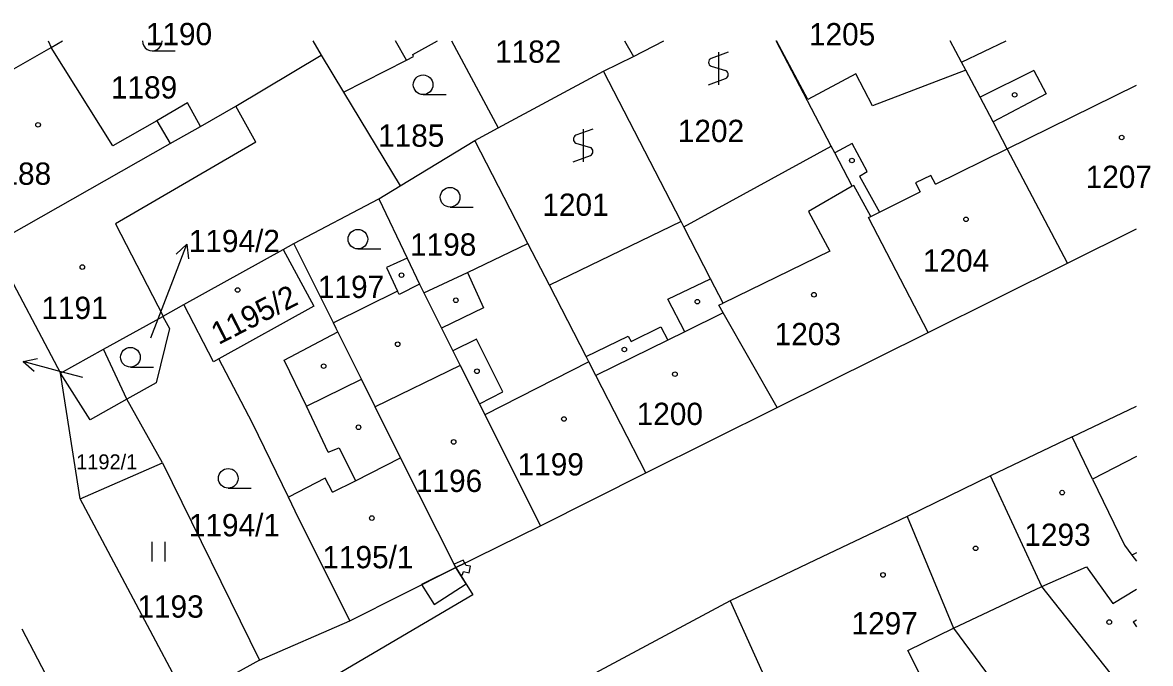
# Model space of a CAD drawing. Extents: x -600849 to -599899, y -1204328 to -1203436.
# Drawn here: x -599989.4 to -599903.3, y -1203485.7 to -1203436.8 of the extents above; entities that cross this region are included whole.
import ezdxf

# ---------------------------------------------------------------- set-up
doc = ezdxf.new("R2010")
doc.units = 0
for name, color, linetype in [('Vrstva 1', 7, 'Continuous'), ('Vrstva 13', 7, 'Continuous'), ('Vrstva 2', 7, 'Continuous'), ('Vrstva 3', 7, 'Continuous'), ('Vrstva 4', 7, 'Continuous'), ('Vrstva 5', 7, 'Continuous'), ('Vrstva 7', 7, 'Continuous')]:
    doc.layers.add(name, color=color, linetype=linetype)

msp = doc.modelspace()

# ---------------------------------------------------------------- linework, layer by layer
at = {"layer": 'Vrstva 1'}
for p, q in [((-599987.2, -1203438.69), (-599986.32, -1203438.183)), ((-599967.221, -1203438.183), (-599966.59, -1203439.27)), ((-599956.633, -1203438.183), (-599953.08, -1203444.83)), ((-599943.424, -1203438.183), (-599942.75, -1203439.37)), ((-599942.75, -1203439.37), (-599940.43, -1203438.183)), ((-599927.66, -1203446.22), (-599931.853, -1203438.183)), ((-599917.71, -1203439.81), (-599918.567, -1203438.183)), ((-599996.72, -1203444.1), (-599987.2, -1203438.69)), ((-599966.59, -1203439.27), (-599964.88, -1203442.11)), ((-599945.04, -1203440.5), (-599942.75, -1203439.37)), ((-599917.39, -1203440.42), (-599917.71, -1203439.81)), ((-599953.08, -1203444.83), (-599945.04, -1203440.5)), ((-599939.12, -1203451.96), (-599945.04, -1203440.5)), ((-599964.88, -1203442.11), (-599960.57, -1203449.26)), ((-599954.85, -1203445.79), (-599953.08, -1203444.83)), ((-599960.57, -1203449.26), (-599954.85, -1203445.79)), ((-599950.81, -1203453.64), (-599954.85, -1203445.79)), ((-599938.91, -1203452.38), (-599927.66, -1203446.22)), ((-599962.19, -1203450.25), (-599960.57, -1203449.26)), ((-599968.67, -1203453.64), (-599962.19, -1203450.25)), ((-599962.19, -1203450.25), (-599960.03, -1203454.76)), ((-599939.12, -1203451.96), (-599949.17, -1203456.84)), ((-599938.91, -1203452.38), (-599939.12, -1203451.96)), ((-599909.61, -1203455.15), (-599904.368, -1203452.529)), ((-599991.69, -1203453.72), (-599986.49, -1203463.55)), ((-599969.49, -1203454.1), (-599968.67, -1203453.64)), ((-599965.65, -1203459.71), (-599968.67, -1203453.64)), ((-599955.41, -1203455.86), (-599950.81, -1203453.64)), ((-599949.17, -1203456.84), (-599950.81, -1203453.64)), ((-599977.06, -1203458.31), (-599969.49, -1203454.1)), ((-599920.25, -1203460.44), (-599909.61, -1203455.15)), ((-599958.76, -1203457.42), (-599955.41, -1203455.86)), ((-599983.2, -1203461.72), (-599978.68, -1203459.21)), ((-599965.44, -1203460.13), (-599965.65, -1203459.71)), ((-599931.78, -1203466.17), (-599920.25, -1203460.44)), ((-599986.49, -1203463.55), (-599983.2, -1203461.72)), ((-599981.42, -1203465.53), (-599983.2, -1203461.72)), ((-599984.97, -1203473.12), (-599986.49, -1203463.55)), ((-599978.69, -1203470.38), (-599981.42, -1203465.53)), ((-599941.8, -1203471.14), (-599931.78, -1203466.17)), ((-599909.27, -1203468.41), (-599915.51, -1203471.39)), ((-599907.72, -1203471.62), (-599909.27, -1203468.41)), ((-599984.97, -1203473.12), (-599978.69, -1203470.38)), ((-599978.69, -1203470.38), (-599971.29, -1203485.45)), ((-599949.85, -1203475.19), (-599941.8, -1203471.14)), ((-599915.51, -1203471.39), (-599921.86, -1203474.48)), ((-599907.72, -1203471.62), (-599905.28, -1203476.67)), ((-599976.82, -1203488.46), (-599984.97, -1203473.12)), ((-599964.39, -1203482.44), (-599968.57, -1203474.08)), ((-599921.86, -1203474.48), (-599928.88, -1203477.8)), ((-599921.86, -1203474.48), (-599918.33, -1203482.99)), ((-599956.31, -1203478.36), (-599949.85, -1203475.19)), ((-599928.88, -1203477.8), (-599935.36, -1203480.92)), ((-599964.39, -1203482.44), (-599956.31, -1203478.36)), ((-599935.36, -1203480.92), (-599947.47, -1203487.4)), ((-599971.29, -1203485.45), (-599964.39, -1203482.44)), ((-599989.43, -1203483.06), (-599984.64, -1203492.24)), ((-599971.29, -1203485.45), (-599976.82, -1203488.46))]:
    msp.add_line(p, q, dxfattribs=at)
for points in [[(-599987.437, -1203438.183), (-599987.2, -1203438.69)], [(-599964.88, -1203442.11), (-599960.07, -1203439.65), (-599959.53, -1203439.37), (-599959.6, -1203439.24), (-599957.709, -1203438.183)], [(-599917.39, -1203440.42), (-599924.5, -1203443.15), (-599925.79, -1203440.7), (-599929.45, -1203442.66), (-599931.824, -1203438.183)], [(-599917.71, -1203439.81), (-599914.3, -1203438.183)], [(-599975.81, -1203444.72), (-599976.8, -1203442.91), (-599979.14, -1203444.29), (-599982.5, -1203446.2), (-599987.2, -1203438.69)], [(-599975.81, -1203444.72), (-599973.09, -1203443.17), (-599966.59, -1203439.27)], [(-599909.61, -1203455.15), (-599914.22, -1203446.42), (-599915.3, -1203444.37), (-599916.29, -1203442.49), (-599917.39, -1203440.42)], [(-599991.69, -1203453.72), (-599978.11, -1203446.02), (-599975.81, -1203444.72)], [(-599920.25, -1203460.44), (-599924.82, -1203451.67), (-599924.64, -1203451.58), (-599925.94, -1203449.22), (-599926.06, -1203449.28), (-599927.39, -1203446.73), (-599927.66, -1203446.22)], [(-599931.78, -1203466.17), (-599935.9, -1203458.93), (-599936.23, -1203458.36), (-599935.9, -1203458.2), (-599936.86, -1203456.35), (-599938.91, -1203452.38)], [(-599969.49, -1203454.1), (-599967.14, -1203458.44), (-599974.39, -1203462.44)], [(-599960.03, -1203454.76), (-599961.59, -1203455.47), (-599960.75, -1203457.28), (-599965.65, -1203459.71)], [(-599960.03, -1203454.76), (-599959.08, -1203456.75), (-599958.76, -1203457.42)], [(-599958.76, -1203457.42), (-599957.4, -1203460.12), (-599956.53, -1203461.85), (-599955.98, -1203462.97), (-599954.51, -1203465.89), (-599954.09, -1203466.73), (-599949.85, -1203475.19)], [(-599941.8, -1203471.14), (-599945.62, -1203463.73), (-599946.15, -1203462.69), (-599946.37, -1203462.27), (-599949.17, -1203456.84)], [(-599978.68, -1203459.21), (-599978.64, -1203459.19), (-599977.06, -1203458.31)], [(-599974.39, -1203462.44), (-599974.8, -1203462.67), (-599977.06, -1203458.31)], [(-599978.68, -1203459.21), (-599978.16, -1203460.14), (-599979.18, -1203464.28), (-599981.42, -1203465.53)], [(-599962.46, -1203466.12), (-599963.51, -1203464.01), (-599965.32, -1203460.38), (-599965.44, -1203460.13)], [(-599968.57, -1203474.08), (-599969.09, -1203473), (-599971.83, -1203467.37), (-599974.39, -1203462.44)], [(-599981.42, -1203465.53), (-599984.23, -1203467.1), (-599986.49, -1203463.55)], [(-599956.31, -1203478.36), (-599960.53, -1203470.01), (-599962.46, -1203466.12)], [(-599909.27, -1203468.41), (-599904.368, -1203466.053)], [(-599904.368, -1203469.911), (-599907.72, -1203471.62)], [(-599905.28, -1203476.67), (-599904.71, -1203477.43), (-599904.368, -1203477.889)], [(-599956.31, -1203478.36), (-599955.02, -1203480.47), (-599982.23, -1203496.46), (-599984.64, -1203492.24)], [(-599935.36, -1203480.92), (-599931.65, -1203489.15), (-599926.92, -1203494.14)], [(-599918.33, -1203482.99), (-599913, -1203490.21), (-599909.83, -1203494.28)]]:
    msp.add_lwpolyline(points, dxfattribs=at)
at = {"layer": 'Vrstva 13'}
for points in [[(-599956.43, -1203478.13), (-599956.31, -1203478.36), (-599955.63, -1203478.03), (-599955.74, -1203477.8)], [(-599956.31, -1203478.36), (-599955.93, -1203478.99), (-599955.79, -1203478.9), (-599955.72, -1203478.69), (-599955.29, -1203478.77), (-599955.2, -1203478.28), (-599955.53, -1203478.22), (-599955.63, -1203478.03)], [(-599958.93, -1203479.68), (-599957.95, -1203481.19), (-599955.53, -1203479.63), (-599955.93, -1203478.99), (-599956.31, -1203478.36)]]:
    msp.add_lwpolyline(points, close=True, dxfattribs=at)
at = {"layer": 'Vrstva 3'}
for p, q in [((-599979.483, -1203438.94), (-599977.733, -1203438.94)), ((-599935.521, -1203439.05), (-599936.821, -1203439.527)), ((-599936.27, -1203439.05), (-599936.27, -1203441.55)), ((-599936.821, -1203440.13), (-599935.719, -1203440.461)), ((-599937.021, -1203441.55), (-599935.719, -1203441.064)), ((-599958.803, -1203442.29), (-599957.053, -1203442.29)), ((-599945.841, -1203444.92), (-599947.141, -1203445.397)), ((-599946.59, -1203444.92), (-599946.59, -1203447.42)), ((-599947.141, -1203446), (-599946.039, -1203446.331)), ((-599947.341, -1203447.42), (-599946.039, -1203446.934)), ((-599956.743, -1203450.87), (-599954.993, -1203450.87)), ((-599963.783, -1203454.07), (-599962.033, -1203454.07)), ((-599981.143, -1203463.08), (-599979.393, -1203463.08)), ((-599973.683, -1203472.32), (-599971.933, -1203472.32)), ((-599979.491, -1203477.92), (-599979.491, -1203476.42)), ((-599978.49, -1203477.92), (-599978.49, -1203476.42))]:
    msp.add_line(p, q, dxfattribs=at)
for centre in [(-599958.803, -1203441.54), (-599956.743, -1203450.12), (-599963.783, -1203453.32), (-599981.143, -1203462.33), (-599973.683, -1203471.57)]:
    msp.add_circle(centre, 0.75, dxfattribs=at)
for centre, radius, start, end in [((-599979.483, -1203438.19), 0.75, 179.47953, 0.52046), ((-599936.691, -1203439.828), 0.329, 113.579, 246.421), ((-599935.849, -1203440.764), 0.329, 293.574, 66.42599), ((-599947.011, -1203445.698), 0.329, 113.579, 246.421), ((-599946.169, -1203446.634), 0.329, 293.574, 66.42599)]:
    msp.add_arc(centre, radius, start, end, dxfattribs=at)
at = {"layer": 'Vrstva 4'}
for p, q in [((-599960.07, -1203439.65), (-599960.914, -1203438.183)), ((-599912.2, -1203440.45), (-599916.29, -1203442.49)), ((-599912.2, -1203440.45), (-599911.26, -1203442.24)), ((-599914.22, -1203446.42), (-599904.368, -1203441.557)), ((-599911.26, -1203442.24), (-599915.3, -1203444.37)), ((-599971.57, -1203445.91), (-599973.09, -1203443.17)), ((-599979.14, -1203444.29), (-599978.11, -1203446.02)), ((-599971.57, -1203445.91), (-599982.28, -1203452.15)), ((-599926.07, -1203446.02), (-599927.39, -1203446.73)), ((-599924.91, -1203448.16), (-599926.07, -1203446.02)), ((-599919.7, -1203449.12), (-599914.22, -1203446.42)), ((-599925.49, -1203448.52), (-599924.91, -1203448.16)), ((-599925.49, -1203448.52), (-599923.98, -1203451.25)), ((-599920.05, -1203448.45), (-599921.23, -1203449.02)), ((-599919.7, -1203449.12), (-599920.05, -1203448.45)), ((-599926.06, -1203449.28), (-599929.38, -1203451.22)), ((-599923.98, -1203451.25), (-599920.87, -1203449.7)), ((-599921.23, -1203449.02), (-599920.87, -1203449.7)), ((-599929.38, -1203451.22), (-599927.77, -1203454.24)), ((-599924.64, -1203451.58), (-599923.98, -1203451.25)), ((-599982.28, -1203452.15), (-599978.64, -1203459.19)), ((-599927.77, -1203454.24), (-599935.9, -1203458.2)), ((-599955.41, -1203455.86), (-599954.2, -1203458.57)), ((-599940.12, -1203457.91), (-599936.86, -1203456.35)), ((-599960.63, -1203457.54), (-599960.75, -1203457.28)), ((-599959.08, -1203456.75), (-599960.63, -1203457.54)), ((-599938.82, -1203460.38), (-599940.12, -1203457.91)), ((-599954.2, -1203458.57), (-599957.4, -1203460.12)), ((-599935.9, -1203458.93), (-599938.82, -1203460.38)), ((-599942.93, -1203461.13), (-599940.67, -1203460.01)), ((-599940.67, -1203460.01), (-599940.12, -1203461.02)), ((-599969.41, -1203462.54), (-599965.32, -1203460.38)), ((-599954.73, -1203460.95), (-599956.53, -1203461.85)), ((-599952.72, -1203464.97), (-599954.73, -1203460.95)), ((-599946.37, -1203462.27), (-599943.15, -1203460.71)), ((-599943.15, -1203460.71), (-599942.93, -1203461.13)), ((-599938.82, -1203460.38), (-599940.12, -1203461.02)), ((-599940.12, -1203461.02), (-599945.62, -1203463.73)), ((-599967.7, -1203466.06), (-599969.41, -1203462.54)), ((-599946.15, -1203462.69), (-599954.09, -1203466.73)), ((-599955.98, -1203462.97), (-599962.46, -1203466.12)), ((-599967.7, -1203466.06), (-599963.51, -1203464.01)), ((-599954.51, -1203465.89), (-599952.72, -1203464.97)), ((-599966.06, -1203469.57), (-599967.7, -1203466.06)), ((-599966.06, -1203469.57), (-599965.22, -1203469.24)), ((-599965.22, -1203469.24), (-599963.97, -1203471.76)), ((-599963.97, -1203471.76), (-599960.53, -1203470.01)), ((-599966.28, -1203471.56), (-599969.09, -1203473)), ((-599965.71, -1203472.63), (-599966.28, -1203471.56)), ((-599965.71, -1203472.63), (-599963.97, -1203471.76)), ((-599911.58, -1203479.82), (-599915.51, -1203471.39)), ((-599904.46, -1203477.3), (-599904.71, -1203477.43)), ((-599904.368, -1203477.251), (-599904.46, -1203477.3)), ((-599911.58, -1203479.82), (-599908.16, -1203478.32)), ((-599908.16, -1203478.32), (-599906.15, -1203481.13)), ((-599918.33, -1203482.99), (-599911.58, -1203479.82)), ((-599905.37, -1203487.65), (-599911.58, -1203479.82)), ((-599906.15, -1203481.13), (-599904.368, -1203480.025)), ((-599904.62, -1203482.53), (-599904.368, -1203482.36)), ((-599921.82, -1203484.71), (-599918.33, -1203482.99)), ((-599904.62, -1203482.53), (-599904.368, -1203482.901)), ((-599920.91, -1203486.47), (-599921.82, -1203484.71))]:
    msp.add_line(p, q, dxfattribs=at)
at = {"layer": 'Vrstva 5'}
for centre in [(-599913.657, -1203442.309), (-599988.197, -1203444.599), (-599905.487, -1203445.559), (-599926.077, -1203447.319), (-599917.367, -1203451.809), (-599984.817, -1203455.449), (-599960.457, -1203456.069), (-599972.967, -1203457.199), (-599928.977, -1203457.559), (-599956.307, -1203457.979), (-599937.877, -1203458.089), (-599960.747, -1203461.339), (-599943.447, -1203461.739), (-599966.397, -1203463.009), (-599954.697, -1203463.399), (-599939.587, -1203463.619), (-599948.057, -1203467.039), (-599963.737, -1203467.669), (-599956.477, -1203468.789), (-599910.027, -1203472.659), (-599962.717, -1203474.599), (-599916.637, -1203476.909), (-599923.707, -1203478.939), (-599906.437, -1203482.539)]:
    msp.add_circle(centre, 0.175, dxfattribs=at)
at = {"layer": 'Vrstva 7'}
for p, q in [((-599977.91, -1203456.5), (-599976.835, -1203453.698)), ((-599976.835, -1203453.698), (-599977.661, -1203454.454)), ((-599976.835, -1203453.698), (-599976.726, -1203454.813)), ((-599979.58, -1203460.85), (-599977.91, -1203456.5)), ((-599989.329, -1203462.653), (-599988.232, -1203462.429)), ((-599986.43, -1203463.43), (-599989.329, -1203462.653)), ((-599989.329, -1203462.653), (-599988.491, -1203463.396)), ((-599984.79, -1203463.88), (-599986.43, -1203463.43))]:
    msp.add_line(p, q, dxfattribs=at)

# ---------------------------------------------------------------- texts
at = {"layer": 'Vrstva 2'}
for s, height, p in [('1190', 1.7, (-599979.968, -1203438.518)), ('1205', 1.7, (-599929.354, -1203438.53)), ('1182', 1.7, (-599953.314, -1203439.86)), ('1189', 1.7, (-599982.634, -1203442.59)), ('1185', 1.7, (-599962.244, -1203446.27)), ('1202', 1.7, (-599939.364, -1203445.91)), ('1188', 1.7, (-599992.254, -1203449.17)), ('1207', 1.7, (-599908.234, -1203449.41)), ('1201', 1.7, (-599949.704, -1203451.54)), ('1194/2', 1.7, (-599976.69, -1203454.31)), ('1198', 1.7, (-599959.804, -1203454.58)), ('1204', 1.7, (-599920.654, -1203455.8)), ('1197', 1.7, (-599966.834, -1203457.81)), ('1191', 1.7, (-599987.944, -1203459.41)), ('1203', 1.7, (-599931.974, -1203461.41)), ('1200', 1.7, (-599942.504, -1203467.5)), ('1192/1', 1.14, (-599985.287, -1203470.88)), ('1199', 1.7, (-599951.594, -1203471.35)), ('1196', 1.7, (-599959.354, -1203472.61)), ('1194/1', 1.7, (-599976.687, -1203475.99)), ('1293', 1.7, (-599912.914, -1203476.72)), ('1195/1', 1.7, (-599966.497, -1203478.43)), ('1193', 1.7, (-599980.614, -1203482.2)), ('1297', 1.7, (-599926.104, -1203483.48))]:
    msp.add_text(s, height=height, dxfattribs=at).set_placement(p)
msp.add_text('1195/2', height=1.7, rotation=27, dxfattribs=at).set_placement((-599974.421, -1203461.409))

doc.saveas('drawing.dxf')
